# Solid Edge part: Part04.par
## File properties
Author: Robert a Rhodes jr
Template: Normal.par
Last saved by: TIET
Revision: 5
Application: Solid Edge
Accuracy: 0.99
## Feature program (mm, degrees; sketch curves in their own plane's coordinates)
body "unnamed Body 1"
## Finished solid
Body 1: solid body, 43 faces, 102 edges, 68 vertices.
  Faces by surface: cylinder 28, plane 15
  Edges by curve: circle 56, line 46
Bounding box of the edges (mm): 1353.852 x 457.200 x 1295.400, from (-676.9261, -203.2, -533.4) to (676.9261, 254, 762).
Cylindrical faces by radius (mm): R50.8 x6, R95.25 x6, R127 x5, R152.4 x2, R254 x2, R431.8 x2, R508 x2, R533.4 x3
Planar faces by outward normal: +x 1, +y 7, -x 1, -y 2, oblique 4
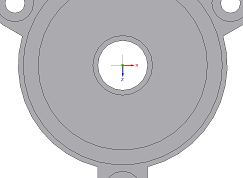
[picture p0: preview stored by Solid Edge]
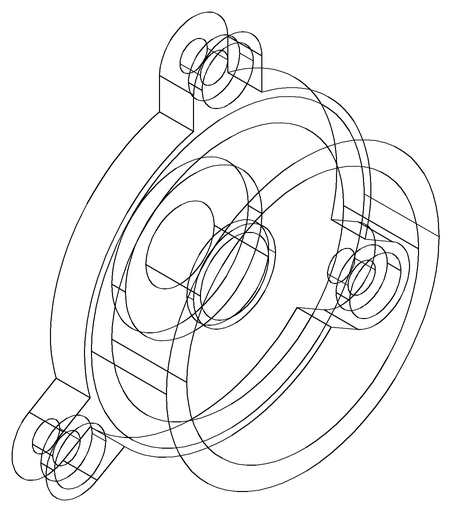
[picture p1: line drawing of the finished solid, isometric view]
